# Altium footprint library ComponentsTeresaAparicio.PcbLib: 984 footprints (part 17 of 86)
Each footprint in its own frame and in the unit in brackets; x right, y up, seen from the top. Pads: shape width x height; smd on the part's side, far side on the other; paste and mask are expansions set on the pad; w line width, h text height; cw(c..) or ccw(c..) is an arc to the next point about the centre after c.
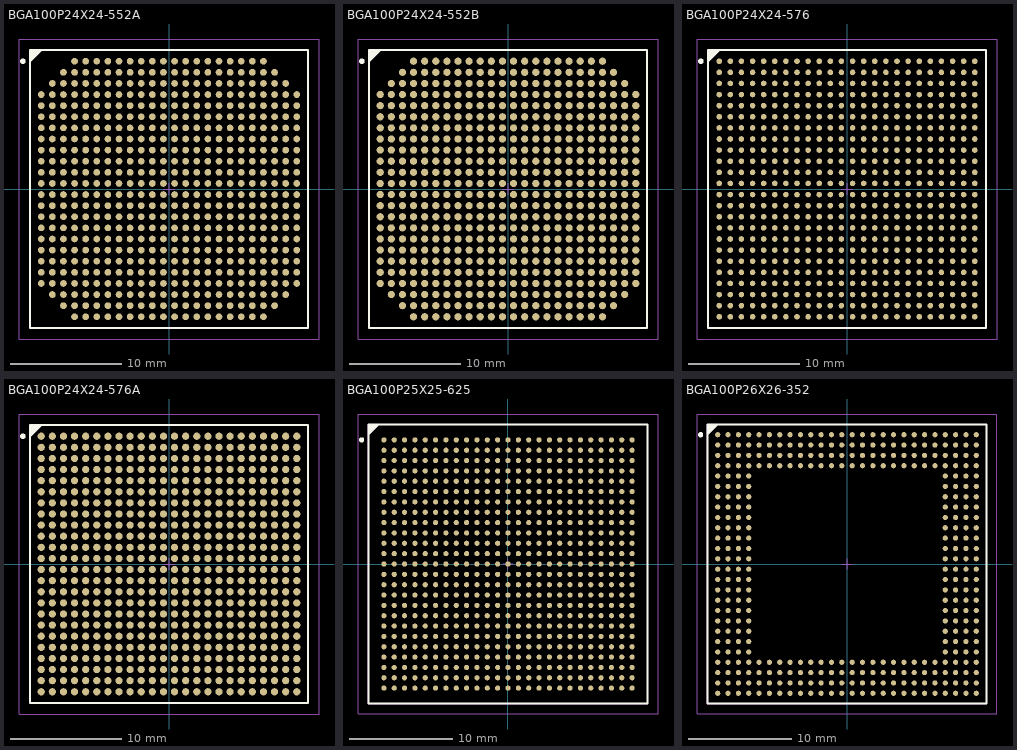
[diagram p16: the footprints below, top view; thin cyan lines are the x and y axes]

## BGA100P24X24-552A [mm] "BGA, 552-Leads, Body 25x25mm, Pitch 1mm"
height 3.49
pads (552):
  round 0.6 smd: A4(-8.5,11.5) A5(-7.5,11.5) A6(-6.5,11.5) A7(-5.5,11.5) A8(-4.5,11.5) A9(-3.5,11.5) A10(-2.5,11.5) A11(-1.5,11.5) A12(-0.5,11.5) A13(0.5,11.5) A14(1.5,11.5) A15(2.5,11.5) A16(3.5,11.5) A17(4.5,11.5) A18(5.5,11.5) A19(6.5,11.5) A20(7.5,11.5) A21(8.5,11.5) AA1(-11.5,-8.5) AA2(-10.5,-8.5) AA3(-9.5,-8.5) AA4(-8.5,-8.5) AA5(-7.5,-8.5) AA6(-6.5,-8.5) AA7(-5.5,-8.5) AA8(-4.5,-8.5) AA9(-3.5,-8.5) AA10(-2.5,-8.5) AA11(-1.5,-8.5) AA12(-0.5,-8.5) AA13(0.5,-8.5) AA14(1.5,-8.5) AA15(2.5,-8.5) AA16(3.5,-8.5) AA17(4.5,-8.5) AA18(5.5,-8.5) AA19(6.5,-8.5) AA20(7.5,-8.5) AA21(8.5,-8.5) AA22(9.5,-8.5) AA23(10.5,-8.5) AA24(11.5,-8.5) AB2(-10.5,-9.5) AB3(-9.5,-9.5) AB4(-8.5,-9.5) AB5(-7.5,-9.5) AB6(-6.5,-9.5) AB7(-5.5,-9.5) AB8(-4.5,-9.5) AB9(-3.5,-9.5) AB10(-2.5,-9.5) AB11(-1.5,-9.5) AB12(-0.5,-9.5) AB13(0.5,-9.5) AB14(1.5,-9.5) AB15(2.5,-9.5) AB16(3.5,-9.5) AB17(4.5,-9.5) AB18(5.5,-9.5) AB19(6.5,-9.5) AB20(7.5,-9.5) AB21(8.5,-9.5) AB22(9.5,-9.5) AB23(10.5,-9.5) AC3(-9.5,-10.5) AC4(-8.5,-10.5) AC5(-7.5,-10.5) AC6(-6.5,-10.5) AC7(-5.5,-10.5) AC8(-4.5,-10.5) AC9(-3.5,-10.5) AC10(-2.5,-10.5) AC11(-1.5,-10.5) AC12(-0.5,-10.5) AC13(0.5,-10.5) AC14(1.5,-10.5) AC15(2.5,-10.5) AC16(3.5,-10.5) AC17(4.5,-10.5) AC18(5.5,-10.5) AC19(6.5,-10.5) AC20(7.5,-10.5) AC21(8.5,-10.5) AC22(9.5,-10.5) AD4(-8.5,-11.5) AD5(-7.5,-11.5) AD6(-6.5,-11.5) AD7(-5.5,-11.5) AD8(-4.5,-11.5) AD9(-3.5,-11.5) AD10(-2.5,-11.5) AD11(-1.5,-11.5) AD12(-0.5,-11.5) AD13(0.5,-11.5) AD14(1.5,-11.5) AD15(2.5,-11.5) AD16(3.5,-11.5) AD17(4.5,-11.5) AD18(5.5,-11.5) AD19(6.5,-11.5) AD20(7.5,-11.5) AD21(8.5,-11.5) B3(-9.5,10.5) B4(-8.5,10.5) B5(-7.5,10.5) B6(-6.5,10.5) B7(-5.5,10.5) B8(-4.5,10.5) B9(-3.5,10.5) B10(-2.5,10.5) B11(-1.5,10.5) B12(-0.5,10.5) B13(0.5,10.5) B14(1.5,10.5) B15(2.5,10.5) B16(3.5,10.5) B17(4.5,10.5) B18(5.5,10.5) B19(6.5,10.5) B20(7.5,10.5) B21(8.5,10.5) B22(9.5,10.5) C2(-10.5,9.5) C3(-9.5,9.5) C4(-8.5,9.5) C5(-7.5,9.5) C6(-6.5,9.5) C7(-5.5,9.5) C8(-4.5,9.5) C9(-3.5,9.5) C10(-2.5,9.5) C11(-1.5,9.5) C12(-0.5,9.5) C13(0.5,9.5) C14(1.5,9.5) C15(2.5,9.5) C16(3.5,9.5) C17(4.5,9.5) C18(5.5,9.5) C19(6.5,9.5) C20(7.5,9.5) C21(8.5,9.5) C22(9.5,9.5) C23(10.5,9.5) D1(-11.5,8.5) D2(-10.5,8.5) D3(-9.5,8.5) D4(-8.5,8.5) D5(-7.5,8.5) D6(-6.5,8.5) D7(-5.5,8.5) D8(-4.5,8.5) D9(-3.5,8.5) D10(-2.5,8.5) D11(-1.5,8.5) D12(-0.5,8.5) D13(0.5,8.5) D14(1.5,8.5) D15(2.5,8.5) D16(3.5,8.5) D17(4.5,8.5) D18(5.5,8.5) D19(6.5,8.5) D20(7.5,8.5) D21(8.5,8.5) D22(9.5,8.5) D23(10.5,8.5) D24(11.5,8.5) E1(-11.5,7.5) E2(-10.5,7.5) E3(-9.5,7.5) E4(-8.5,7.5) E5(-7.5,7.5) E6(-6.5,7.5) E7(-5.5,7.5) E8(-4.5,7.5) E9(-3.5,7.5) E10(-2.5,7.5) E11(-1.5,7.5) E12(-0.5,7.5) E13(0.5,7.5) E14(1.5,7.5) E15(2.5,7.5) E16(3.5,7.5) E17(4.5,7.5) E18(5.5,7.5) E19(6.5,7.5) E20(7.5,7.5) E21(8.5,7.5) E22(9.5,7.5) E23(10.5,7.5) E24(11.5,7.5) F1(-11.5,6.5) F2(-10.5,6.5) F3(-9.5,6.5) F4(-8.5,6.5) F5(-7.5,6.5) F6(-6.5,6.5) F7(-5.5,6.5) F8(-4.5,6.5) F9(-3.5,6.5) F10(-2.5,6.5) F11(-1.5,6.5) F12(-0.5,6.5) F13(0.5,6.5) F14(1.5,6.5) F15(2.5,6.5) F16(3.5,6.5) F17(4.5,6.5) F18(5.5,6.5) F19(6.5,6.5) F20(7.5,6.5) F21(8.5,6.5) F22(9.5,6.5) F23(10.5,6.5) F24(11.5,6.5) G1(-11.5,5.5) G2(-10.5,5.5) G3(-9.5,5.5) G4(-8.5,5.5) G5(-7.5,5.5) G6(-6.5,5.5) G7(-5.5,5.5) G8(-4.5,5.5) G9(-3.5,5.5) G10(-2.5,5.5) G11(-1.5,5.5) G12(-0.5,5.5) G13(0.5,5.5) G14(1.5,5.5) G15(2.5,5.5) G16(3.5,5.5) G17(4.5,5.5) G18(5.5,5.5) G19(6.5,5.5) G20(7.5,5.5) G21(8.5,5.5) G22(9.5,5.5) G23(10.5,5.5) G24(11.5,5.5) H1(-11.5,4.5) H2(-10.5,4.5) H3(-9.5,4.5) H4(-8.5,4.5) H5(-7.5,4.5) H6(-6.5,4.5) H7(-5.5,4.5) H8(-4.5,4.5) H9(-3.5,4.5) H10(-2.5,4.5) H11(-1.5,4.5) H12(-0.5,4.5) H13(0.5,4.5) H14(1.5,4.5) H15(2.5,4.5) H16(3.5,4.5) H17(4.5,4.5) H18(5.5,4.5) H19(6.5,4.5) H20(7.5,4.5) H21(8.5,4.5) H22(9.5,4.5) H23(10.5,4.5) H24(11.5,4.5) J1(-11.5,3.5) J2(-10.5,3.5) J3(-9.5,3.5) J4(-8.5,3.5) J5(-7.5,3.5) J6(-6.5,3.5) J7(-5.5,3.5) J8(-4.5,3.5) J9(-3.5,3.5) J10(-2.5,3.5) J11(-1.5,3.5) J12(-0.5,3.5) J13(0.5,3.5) J14(1.5,3.5) J15(2.5,3.5) J16(3.5,3.5) J17(4.5,3.5) J18(5.5,3.5) J19(6.5,3.5) J20(7.5,3.5) J21(8.5,3.5) J22(9.5,3.5) J23(10.5,3.5) J24(11.5,3.5) K1(-11.5,2.5) K2(-10.5,2.5) K3(-9.5,2.5) K4(-8.5,2.5) K5(-7.5,2.5) K6(-6.5,2.5) K7(-5.5,2.5) K8(-4.5,2.5) K9(-3.5,2.5) K10(-2.5,2.5) K11(-1.5,2.5) K12(-0.5,2.5) K13(0.5,2.5) K14(1.5,2.5) K15(2.5,2.5) K16(3.5,2.5) K17(4.5,2.5) K18(5.5,2.5) K19(6.5,2.5) K20(7.5,2.5) K21(8.5,2.5) K22(9.5,2.5) K23(10.5,2.5) K24(11.5,2.5) L1(-11.5,1.5) L2(-10.5,1.5) L3(-9.5,1.5) L4(-8.5,1.5) L5(-7.5,1.5) L6(-6.5,1.5) L7(-5.5,1.5) L8(-4.5,1.5) L9(-3.5,1.5) L10(-2.5,1.5) L11(-1.5,1.5) L12(-0.5,1.5) L13(0.5,1.5) L14(1.5,1.5) L15(2.5,1.5) L16(3.5,1.5) L17(4.5,1.5) L18(5.5,1.5) L19(6.5,1.5) L20(7.5,1.5) L21(8.5,1.5) L22(9.5,1.5) L23(10.5,1.5) L24(11.5,1.5) M1(-11.5,0.5) M2(-10.5,0.5) M3(-9.5,0.5) M4(-8.5,0.5) M5(-7.5,0.5) M6(-6.5,0.5) M7(-5.5,0.5) M8(-4.5,0.5) M9(-3.5,0.5) M10(-2.5,0.5) M11(-1.5,0.5) M12(-0.5,0.5) M13(0.5,0.5) M14(1.5,0.5) M15(2.5,0.5) M16(3.5,0.5) M17(4.5,0.5) M18(5.5,0.5) M19(6.5,0.5) M20(7.5,0.5) M21(8.5,0.5) M22(9.5,0.5) M23(10.5,0.5) M24(11.5,0.5) N1(-11.5,-0.5) N2(-10.5,-0.5) N3(-9.5,-0.5) N4(-8.5,-0.5) N5(-7.5,-0.5) N6(-6.5,-0.5) N7(-5.5,-0.5) N8(-4.5,-0.5) N9(-3.5,-0.5) N10(-2.5,-0.5) N11(-1.5,-0.5) N12(-0.5,-0.5) N13(0.5,-0.5) N14(1.5,-0.5) N15(2.5,-0.5) N16(3.5,-0.5) N17(4.5,-0.5) N18(5.5,-0.5) N19(6.5,-0.5) N20(7.5,-0.5) N21(8.5,-0.5) N22(9.5,-0.5) N23(10.5,-0.5) N24(11.5,-0.5) P1(-11.5,-1.5) P2(-10.5,-1.5) P3(-9.5,-1.5) P4(-8.5,-1.5) P5(-7.5,-1.5) P6(-6.5,-1.5) P7(-5.5,-1.5) P8(-4.5,-1.5) P9(-3.5,-1.5) P10(-2.5,-1.5) P11(-1.5,-1.5) P12(-0.5,-1.5) P13(0.5,-1.5) P14(1.5,-1.5) P15(2.5,-1.5) P16(3.5,-1.5) P17(4.5,-1.5) P18(5.5,-1.5) P19(6.5,-1.5) P20(7.5,-1.5) P21(8.5,-1.5) P22(9.5,-1.5) P23(10.5,-1.5) P24(11.5,-1.5) R1(-11.5,-2.5) R2(-10.5,-2.5) R3(-9.5,-2.5) R4(-8.5,-2.5) R5(-7.5,-2.5) R6(-6.5,-2.5) R7(-5.5,-2.5) R8(-4.5,-2.5) R9(-3.5,-2.5) R10(-2.5,-2.5) R11(-1.5,-2.5) R12(-0.5,-2.5) R13(0.5,-2.5) R14(1.5,-2.5) R15(2.5,-2.5) R16(3.5,-2.5) R17(4.5,-2.5) R18(5.5,-2.5) R19(6.5,-2.5) R20(7.5,-2.5) R21(8.5,-2.5) R22(9.5,-2.5) R23(10.5,-2.5) R24(11.5,-2.5) T1(-11.5,-3.5) T2(-10.5,-3.5) T3(-9.5,-3.5) T4(-8.5,-3.5) T5(-7.5,-3.5) T6(-6.5,-3.5) T7(-5.5,-3.5) T8(-4.5,-3.5) T9(-3.5,-3.5) T10(-2.5,-3.5) T11(-1.5,-3.5) T12(-0.5,-3.5) T13(0.5,-3.5) T14(1.5,-3.5) T15(2.5,-3.5) T16(3.5,-3.5) T17(4.5,-3.5) T18(5.5,-3.5) T19(6.5,-3.5) T20(7.5,-3.5) T21(8.5,-3.5) T22(9.5,-3.5) T23(10.5,-3.5) T24(11.5,-3.5) U1(-11.5,-4.5) U2(-10.5,-4.5) U3(-9.5,-4.5) U4(-8.5,-4.5) U5(-7.5,-4.5) U6(-6.5,-4.5) U7(-5.5,-4.5) U8(-4.5,-4.5) U9(-3.5,-4.5) U10(-2.5,-4.5) U11(-1.5,-4.5) U12(-0.5,-4.5) U13(0.5,-4.5) U14(1.5,-4.5) U15(2.5,-4.5) U16(3.5,-4.5) U17(4.5,-4.5) U18(5.5,-4.5) U19(6.5,-4.5) U20(7.5,-4.5) U21(8.5,-4.5) U22(9.5,-4.5) U23(10.5,-4.5) U24(11.5,-4.5) V1(-11.5,-5.5) V2(-10.5,-5.5) V3(-9.5,-5.5) V4(-8.5,-5.5) V5(-7.5,-5.5) V6(-6.5,-5.5) V7(-5.5,-5.5) V8(-4.5,-5.5) V9(-3.5,-5.5) V10(-2.5,-5.5) V11(-1.5,-5.5) V12(-0.5,-5.5) V13(0.5,-5.5) V14(1.5,-5.5) V15(2.5,-5.5) V16(3.5,-5.5) V17(4.5,-5.5) V18(5.5,-5.5) V19(6.5,-5.5) V20(7.5,-5.5) V21(8.5,-5.5) V22(9.5,-5.5) V23(10.5,-5.5) V24(11.5,-5.5) W1(-11.5,-6.5) W2(-10.5,-6.5) W3(-9.5,-6.5) W4(-8.5,-6.5) W5(-7.5,-6.5) W6(-6.5,-6.5) W7(-5.5,-6.5) W8(-4.5,-6.5) W9(-3.5,-6.5) W10(-2.5,-6.5) W11(-1.5,-6.5) W12(-0.5,-6.5) W13(0.5,-6.5) W14(1.5,-6.5) W15(2.5,-6.5) W16(3.5,-6.5) W17(4.5,-6.5) W18(5.5,-6.5) W19(6.5,-6.5) W20(7.5,-6.5) W21(8.5,-6.5) W22(9.5,-6.5) W23(10.5,-6.5) W24(11.5,-6.5) Y1(-11.5,-7.5) Y2(-10.5,-7.5) Y3(-9.5,-7.5) Y4(-8.5,-7.5) Y5(-7.5,-7.5) Y6(-6.5,-7.5) Y7(-5.5,-7.5) Y8(-4.5,-7.5) Y9(-3.5,-7.5) Y10(-2.5,-7.5) Y11(-1.5,-7.5) Y12(-0.5,-7.5) Y13(0.5,-7.5) Y14(1.5,-7.5) Y15(2.5,-7.5) Y16(3.5,-7.5) Y17(4.5,-7.5) Y18(5.5,-7.5) Y19(6.5,-7.5) Y20(7.5,-7.5) Y21(8.5,-7.5) Y22(9.5,-7.5) Y23(10.5,-7.5) Y24(11.5,-7.5)
Top Overlay:
  circle w0.25: c-13.15,11.5 r0.125
  region: -11.5,12.5 -12.5,11.5 -12.5,12.5
  lines w0.2: -12.5,11.5 -11.5,12.5 ; -12.5,-12.5 -12.5,12.5 12.5,12.5 12.5,-12.5 -12.5,-12.5
Mechanical 13:
  lines w0.1: -12.5,-12.5 -12.5,12.5 12.5,12.5 12.5,-12.5 -12.5,-12.5
Mechanical 15:
  lines w0.1: -0.5,0 0.5,0 ; 0,-0.5 0,0.5 ; -13.5,-13.5 -13.5,13.5 13.5,13.5 13.5,-13.5 -13.5,-13.5
3D body: height 0, standoff 0, extent -12.5,-12.5 12.5,12.5

## BGA100P24X24-552B [mm] "BGA, 552-Leads, Body 25x25mm, Pitch 1mm"
height 3.8
pads (552):
  round 0.65 smd: A4(-8.5,11.5) A5(-7.5,11.5) A6(-6.5,11.5) A7(-5.5,11.5) A8(-4.5,11.5) A9(-3.5,11.5) A10(-2.5,11.5) A11(-1.5,11.5) A12(-0.5,11.5) A13(0.5,11.5) A14(1.5,11.5) A15(2.5,11.5) A16(3.5,11.5) A17(4.5,11.5) A18(5.5,11.5) A19(6.5,11.5) A20(7.5,11.5) A21(8.5,11.5) AA1(-11.5,-8.5) AA2(-10.5,-8.5) AA3(-9.5,-8.5) AA4(-8.5,-8.5) AA5(-7.5,-8.5) AA6(-6.5,-8.5) AA7(-5.5,-8.5) AA8(-4.5,-8.5) AA9(-3.5,-8.5) AA10(-2.5,-8.5) AA11(-1.5,-8.5) AA12(-0.5,-8.5) AA13(0.5,-8.5) AA14(1.5,-8.5) AA15(2.5,-8.5) AA16(3.5,-8.5) AA17(4.5,-8.5) AA18(5.5,-8.5) AA19(6.5,-8.5) AA20(7.5,-8.5) AA21(8.5,-8.5) AA22(9.5,-8.5) AA23(10.5,-8.5) AA24(11.5,-8.5) AB2(-10.5,-9.5) AB3(-9.5,-9.5) AB4(-8.5,-9.5) AB5(-7.5,-9.5) AB6(-6.5,-9.5) AB7(-5.5,-9.5) AB8(-4.5,-9.5) AB9(-3.5,-9.5) AB10(-2.5,-9.5) AB11(-1.5,-9.5) AB12(-0.5,-9.5) AB13(0.5,-9.5) AB14(1.5,-9.5) AB15(2.5,-9.5) AB16(3.5,-9.5) AB17(4.5,-9.5) AB18(5.5,-9.5) AB19(6.5,-9.5) AB20(7.5,-9.5) AB21(8.5,-9.5) AB22(9.5,-9.5) AB23(10.5,-9.5) AC3(-9.5,-10.5) AC4(-8.5,-10.5) AC5(-7.5,-10.5) AC6(-6.5,-10.5) AC7(-5.5,-10.5) AC8(-4.5,-10.5) AC9(-3.5,-10.5) AC10(-2.5,-10.5) AC11(-1.5,-10.5) AC12(-0.5,-10.5) AC13(0.5,-10.5) AC14(1.5,-10.5) AC15(2.5,-10.5) AC16(3.5,-10.5) AC17(4.5,-10.5) AC18(5.5,-10.5) AC19(6.5,-10.5) AC20(7.5,-10.5) AC21(8.5,-10.5) AC22(9.5,-10.5) AD4(-8.5,-11.5) AD5(-7.5,-11.5) AD6(-6.5,-11.5) AD7(-5.5,-11.5) AD8(-4.5,-11.5) AD9(-3.5,-11.5) AD10(-2.5,-11.5) AD11(-1.5,-11.5) AD12(-0.5,-11.5) AD13(0.5,-11.5) AD14(1.5,-11.5) AD15(2.5,-11.5) AD16(3.5,-11.5) AD17(4.5,-11.5) AD18(5.5,-11.5) AD19(6.5,-11.5) AD20(7.5,-11.5) AD21(8.5,-11.5) B3(-9.5,10.5) B4(-8.5,10.5) B5(-7.5,10.5) B6(-6.5,10.5) B7(-5.5,10.5) B8(-4.5,10.5) B9(-3.5,10.5) B10(-2.5,10.5) B11(-1.5,10.5) B12(-0.5,10.5) B13(0.5,10.5) B14(1.5,10.5) B15(2.5,10.5) B16(3.5,10.5) B17(4.5,10.5) B18(5.5,10.5) B19(6.5,10.5) B20(7.5,10.5) B21(8.5,10.5) B22(9.5,10.5) C2(-10.5,9.5) C3(-9.5,9.5) C4(-8.5,9.5) C5(-7.5,9.5) C6(-6.5,9.5) C7(-5.5,9.5) C8(-4.5,9.5) C9(-3.5,9.5) C10(-2.5,9.5) C11(-1.5,9.5) C12(-0.5,9.5) C13(0.5,9.5) C14(1.5,9.5) C15(2.5,9.5) C16(3.5,9.5) C17(4.5,9.5) C18(5.5,9.5) C19(6.5,9.5) C20(7.5,9.5) C21(8.5,9.5) C22(9.5,9.5) C23(10.5,9.5) D1(-11.5,8.5) D2(-10.5,8.5) D3(-9.5,8.5) D4(-8.5,8.5) D5(-7.5,8.5) D6(-6.5,8.5) D7(-5.5,8.5) D8(-4.5,8.5) D9(-3.5,8.5) D10(-2.5,8.5) D11(-1.5,8.5) D12(-0.5,8.5) D13(0.5,8.5) D14(1.5,8.5) D15(2.5,8.5) D16(3.5,8.5) D17(4.5,8.5) D18(5.5,8.5) D19(6.5,8.5) D20(7.5,8.5) D21(8.5,8.5) D22(9.5,8.5) D23(10.5,8.5) D24(11.5,8.5) E1(-11.5,7.5) E2(-10.5,7.5) E3(-9.5,7.5) E4(-8.5,7.5) E5(-7.5,7.5) E6(-6.5,7.5) E7(-5.5,7.5) E8(-4.5,7.5) E9(-3.5,7.5) E10(-2.5,7.5) E11(-1.5,7.5) E12(-0.5,7.5) E13(0.5,7.5) E14(1.5,7.5) E15(2.5,7.5) E16(3.5,7.5) E17(4.5,7.5) E18(5.5,7.5) E19(6.5,7.5) E20(7.5,7.5) E21(8.5,7.5) E22(9.5,7.5) E23(10.5,7.5) E24(11.5,7.5) F1(-11.5,6.5) F2(-10.5,6.5) F3(-9.5,6.5) F4(-8.5,6.5) F5(-7.5,6.5) F6(-6.5,6.5) F7(-5.5,6.5) F8(-4.5,6.5) F9(-3.5,6.5) F10(-2.5,6.5) F11(-1.5,6.5) F12(-0.5,6.5) F13(0.5,6.5) F14(1.5,6.5) F15(2.5,6.5) F16(3.5,6.5) F17(4.5,6.5) F18(5.5,6.5) F19(6.5,6.5) F20(7.5,6.5) F21(8.5,6.5) F22(9.5,6.5) F23(10.5,6.5) F24(11.5,6.5) G1(-11.5,5.5) G2(-10.5,5.5) G3(-9.5,5.5) G4(-8.5,5.5) G5(-7.5,5.5) G6(-6.5,5.5) G7(-5.5,5.5) G8(-4.5,5.5) G9(-3.5,5.5) G10(-2.5,5.5) G11(-1.5,5.5) G12(-0.5,5.5) G13(0.5,5.5) G14(1.5,5.5) G15(2.5,5.5) G16(3.5,5.5) G17(4.5,5.5) G18(5.5,5.5) G19(6.5,5.5) G20(7.5,5.5) G21(8.5,5.5) G22(9.5,5.5) G23(10.5,5.5) G24(11.5,5.5) H1(-11.5,4.5) H2(-10.5,4.5) H3(-9.5,4.5) H4(-8.5,4.5) H5(-7.5,4.5) H6(-6.5,4.5) H7(-5.5,4.5) H8(-4.5,4.5) H9(-3.5,4.5) H10(-2.5,4.5) H11(-1.5,4.5) H12(-0.5,4.5) H13(0.5,4.5) H14(1.5,4.5) H15(2.5,4.5) H16(3.5,4.5) H17(4.5,4.5) H18(5.5,4.5) H19(6.5,4.5) H20(7.5,4.5) H21(8.5,4.5) H22(9.5,4.5) H23(10.5,4.5) H24(11.5,4.5) J1(-11.5,3.5) J2(-10.5,3.5) J3(-9.5,3.5) J4(-8.5,3.5) J5(-7.5,3.5) J6(-6.5,3.5) J7(-5.5,3.5) J8(-4.5,3.5) J9(-3.5,3.5) J10(-2.5,3.5) J11(-1.5,3.5) J12(-0.5,3.5) J13(0.5,3.5) J14(1.5,3.5) J15(2.5,3.5) J16(3.5,3.5) J17(4.5,3.5) J18(5.5,3.5) J19(6.5,3.5) J20(7.5,3.5) J21(8.5,3.5) J22(9.5,3.5) J23(10.5,3.5) J24(11.5,3.5) K1(-11.5,2.5) K2(-10.5,2.5) K3(-9.5,2.5) K4(-8.5,2.5) K5(-7.5,2.5) K6(-6.5,2.5) K7(-5.5,2.5) K8(-4.5,2.5) K9(-3.5,2.5) K10(-2.5,2.5) K11(-1.5,2.5) K12(-0.5,2.5) K13(0.5,2.5) K14(1.5,2.5) K15(2.5,2.5) K16(3.5,2.5) K17(4.5,2.5) K18(5.5,2.5) K19(6.5,2.5) K20(7.5,2.5) K21(8.5,2.5) K22(9.5,2.5) K23(10.5,2.5) K24(11.5,2.5) L1(-11.5,1.5) L2(-10.5,1.5) L3(-9.5,1.5) L4(-8.5,1.5) L5(-7.5,1.5) L6(-6.5,1.5) L7(-5.5,1.5) L8(-4.5,1.5) L9(-3.5,1.5) L10(-2.5,1.5) L11(-1.5,1.5) L12(-0.5,1.5) L13(0.5,1.5) L14(1.5,1.5) L15(2.5,1.5) L16(3.5,1.5) L17(4.5,1.5) L18(5.5,1.5) L19(6.5,1.5) L20(7.5,1.5) L21(8.5,1.5) L22(9.5,1.5) L23(10.5,1.5) L24(11.5,1.5) M1(-11.5,0.5) M2(-10.5,0.5) M3(-9.5,0.5) M4(-8.5,0.5) M5(-7.5,0.5) M6(-6.5,0.5) M7(-5.5,0.5) M8(-4.5,0.5) M9(-3.5,0.5) M10(-2.5,0.5) M11(-1.5,0.5) M12(-0.5,0.5) M13(0.5,0.5) M14(1.5,0.5) M15(2.5,0.5) M16(3.5,0.5) M17(4.5,0.5) M18(5.5,0.5) M19(6.5,0.5) M20(7.5,0.5) M21(8.5,0.5) M22(9.5,0.5) M23(10.5,0.5) M24(11.5,0.5) N1(-11.5,-0.5) N2(-10.5,-0.5) N3(-9.5,-0.5) N4(-8.5,-0.5) N5(-7.5,-0.5) N6(-6.5,-0.5) N7(-5.5,-0.5) N8(-4.5,-0.5) N9(-3.5,-0.5) N10(-2.5,-0.5) N11(-1.5,-0.5) N12(-0.5,-0.5) N13(0.5,-0.5) N14(1.5,-0.5) N15(2.5,-0.5) N16(3.5,-0.5) N17(4.5,-0.5) N18(5.5,-0.5) N19(6.5,-0.5) N20(7.5,-0.5) N21(8.5,-0.5) N22(9.5,-0.5) N23(10.5,-0.5) N24(11.5,-0.5) P1(-11.5,-1.5) P2(-10.5,-1.5) P3(-9.5,-1.5) P4(-8.5,-1.5) P5(-7.5,-1.5) P6(-6.5,-1.5) P7(-5.5,-1.5) P8(-4.5,-1.5) P9(-3.5,-1.5) P10(-2.5,-1.5) P11(-1.5,-1.5) P12(-0.5,-1.5) P13(0.5,-1.5) P14(1.5,-1.5) P15(2.5,-1.5) P16(3.5,-1.5) P17(4.5,-1.5) P18(5.5,-1.5) P19(6.5,-1.5) P20(7.5,-1.5) P21(8.5,-1.5) P22(9.5,-1.5) P23(10.5,-1.5) P24(11.5,-1.5) R1(-11.5,-2.5) R2(-10.5,-2.5) R3(-9.5,-2.5) R4(-8.5,-2.5) R5(-7.5,-2.5) R6(-6.5,-2.5) R7(-5.5,-2.5) R8(-4.5,-2.5) R9(-3.5,-2.5) R10(-2.5,-2.5) R11(-1.5,-2.5) R12(-0.5,-2.5) R13(0.5,-2.5) R14(1.5,-2.5) R15(2.5,-2.5) R16(3.5,-2.5) R17(4.5,-2.5) R18(5.5,-2.5) R19(6.5,-2.5) R20(7.5,-2.5) R21(8.5,-2.5) R22(9.5,-2.5) R23(10.5,-2.5) R24(11.5,-2.5) T1(-11.5,-3.5) T2(-10.5,-3.5) T3(-9.5,-3.5) T4(-8.5,-3.5) T5(-7.5,-3.5) T6(-6.5,-3.5) T7(-5.5,-3.5) T8(-4.5,-3.5) T9(-3.5,-3.5) T10(-2.5,-3.5) T11(-1.5,-3.5) T12(-0.5,-3.5) T13(0.5,-3.5) T14(1.5,-3.5) T15(2.5,-3.5) T16(3.5,-3.5) T17(4.5,-3.5) T18(5.5,-3.5) T19(6.5,-3.5) T20(7.5,-3.5) T21(8.5,-3.5) T22(9.5,-3.5) T23(10.5,-3.5) T24(11.5,-3.5) U1(-11.5,-4.5) U2(-10.5,-4.5) U3(-9.5,-4.5) U4(-8.5,-4.5) U5(-7.5,-4.5) U6(-6.5,-4.5) U7(-5.5,-4.5) U8(-4.5,-4.5) U9(-3.5,-4.5) U10(-2.5,-4.5) U11(-1.5,-4.5) U12(-0.5,-4.5) U13(0.5,-4.5) U14(1.5,-4.5) U15(2.5,-4.5) U16(3.5,-4.5) U17(4.5,-4.5) U18(5.5,-4.5) U19(6.5,-4.5) U20(7.5,-4.5) U21(8.5,-4.5) U22(9.5,-4.5) U23(10.5,-4.5) U24(11.5,-4.5) V1(-11.5,-5.5) V2(-10.5,-5.5) V3(-9.5,-5.5) V4(-8.5,-5.5) V5(-7.5,-5.5) V6(-6.5,-5.5) V7(-5.5,-5.5) V8(-4.5,-5.5) V9(-3.5,-5.5) V10(-2.5,-5.5) V11(-1.5,-5.5) V12(-0.5,-5.5) V13(0.5,-5.5) V14(1.5,-5.5) V15(2.5,-5.5) V16(3.5,-5.5) V17(4.5,-5.5) V18(5.5,-5.5) V19(6.5,-5.5) V20(7.5,-5.5) V21(8.5,-5.5) V22(9.5,-5.5) V23(10.5,-5.5) V24(11.5,-5.5) W1(-11.5,-6.5) W2(-10.5,-6.5) W3(-9.5,-6.5) W4(-8.5,-6.5) W5(-7.5,-6.5) W6(-6.5,-6.5) W7(-5.5,-6.5) W8(-4.5,-6.5) W9(-3.5,-6.5) W10(-2.5,-6.5) W11(-1.5,-6.5) W12(-0.5,-6.5) W13(0.5,-6.5) W14(1.5,-6.5) W15(2.5,-6.5) W16(3.5,-6.5) W17(4.5,-6.5) W18(5.5,-6.5) W19(6.5,-6.5) W20(7.5,-6.5) W21(8.5,-6.5) W22(9.5,-6.5) W23(10.5,-6.5) W24(11.5,-6.5) Y1(-11.5,-7.5) Y2(-10.5,-7.5) Y3(-9.5,-7.5) Y4(-8.5,-7.5) Y5(-7.5,-7.5) Y6(-6.5,-7.5) Y7(-5.5,-7.5) Y8(-4.5,-7.5) Y9(-3.5,-7.5) Y10(-2.5,-7.5) Y11(-1.5,-7.5) Y12(-0.5,-7.5) Y13(0.5,-7.5) Y14(1.5,-7.5) Y15(2.5,-7.5) Y16(3.5,-7.5) Y17(4.5,-7.5) Y18(5.5,-7.5) Y19(6.5,-7.5) Y20(7.5,-7.5) Y21(8.5,-7.5) Y22(9.5,-7.5) Y23(10.5,-7.5) Y24(11.5,-7.5)
Top Overlay:
  circle w0.25: c-13.15,11.5 r0.125
  region: -11.525,12.5 -12.5,11.525 -12.5,12.5
  lines w0.2: -12.5,11.525 -11.525,12.5 ; -12.5,-12.5 12.5,-12.5 12.5,12.5 -12.5,12.5 -12.5,-12.5
Mechanical 13:
  lines w0.1: -12.5,-12.5 12.5,-12.5 12.5,12.5 -12.5,12.5 -12.5,-12.5
Mechanical 15:
  lines w0.1: -0.5,0 0.5,0 ; 0,-0.5 0,0.5 ; -13.5,-13.5 13.5,-13.5 13.5,13.5 -13.5,13.5 -13.5,-13.5
3D body: height 0, standoff 0, extent -12.5,-12.5 12.5,12.5

## BGA100P24X24-576 [mm] "BGA, 576-Leads, Body 25x25mm, Pitch 1mm"
height 3.5
pads (576):
  round 0.5 smd: A1(-11.5,11.5) A2(-10.5,11.5) A3(-9.5,11.5) A4(-8.5,11.5) A5(-7.5,11.5) A6(-6.5,11.5) A7(-5.5,11.5) A8(-4.5,11.5) A9(-3.5,11.5) A10(-2.5,11.5) A11(-1.5,11.5) A12(-0.5,11.5) A13(0.5,11.5) A14(1.5,11.5) A15(2.5,11.5) A16(3.5,11.5) A17(4.5,11.5) A18(5.5,11.5) A19(6.5,11.5) A20(7.5,11.5) A21(8.5,11.5) A22(9.5,11.5) A23(10.5,11.5) A24(11.5,11.5) AA1(-11.5,-8.5) AA2(-10.5,-8.5) AA3(-9.5,-8.5) AA4(-8.5,-8.5) AA5(-7.5,-8.5) AA6(-6.5,-8.5) AA7(-5.5,-8.5) AA8(-4.5,-8.5) AA9(-3.5,-8.5) AA10(-2.5,-8.5) AA11(-1.5,-8.5) AA12(-0.5,-8.5) AA13(0.5,-8.5) AA14(1.5,-8.5) AA15(2.5,-8.5) AA16(3.5,-8.5) AA17(4.5,-8.5) AA18(5.5,-8.5) AA19(6.5,-8.5) AA20(7.5,-8.5) AA21(8.5,-8.5) AA22(9.5,-8.5) AA23(10.5,-8.5) AA24(11.5,-8.5) AB1(-11.5,-9.5) AB2(-10.5,-9.5) AB3(-9.5,-9.5) AB4(-8.5,-9.5) AB5(-7.5,-9.5) AB6(-6.5,-9.5) AB7(-5.5,-9.5) AB8(-4.5,-9.5) AB9(-3.5,-9.5) AB10(-2.5,-9.5) AB11(-1.5,-9.5) AB12(-0.5,-9.5) AB13(0.5,-9.5) AB14(1.5,-9.5) AB15(2.5,-9.5) AB16(3.5,-9.5) AB17(4.5,-9.5) AB18(5.5,-9.5) AB19(6.5,-9.5) AB20(7.5,-9.5) AB21(8.5,-9.5) AB22(9.5,-9.5) AB23(10.5,-9.5) AB24(11.5,-9.5) AC1(-11.5,-10.5) AC2(-10.5,-10.5) AC3(-9.5,-10.5) AC4(-8.5,-10.5) AC5(-7.5,-10.5) AC6(-6.5,-10.5) AC7(-5.5,-10.5) AC8(-4.5,-10.5) AC9(-3.5,-10.5) AC10(-2.5,-10.5) AC11(-1.5,-10.5) AC12(-0.5,-10.5) AC13(0.5,-10.5) AC14(1.5,-10.5) AC15(2.5,-10.5) AC16(3.5,-10.5) AC17(4.5,-10.5) AC18(5.5,-10.5) AC19(6.5,-10.5) AC20(7.5,-10.5) AC21(8.5,-10.5) AC22(9.5,-10.5) AC23(10.5,-10.5) AC24(11.5,-10.5) AD1(-11.5,-11.5) AD2(-10.5,-11.5) AD3(-9.5,-11.5) AD4(-8.5,-11.5) AD5(-7.5,-11.5) AD6(-6.5,-11.5) AD7(-5.5,-11.5) AD8(-4.5,-11.5) AD9(-3.5,-11.5) AD10(-2.5,-11.5) AD11(-1.5,-11.5) AD12(-0.5,-11.5) AD13(0.5,-11.5) AD14(1.5,-11.5) AD15(2.5,-11.5) AD16(3.5,-11.5) AD17(4.5,-11.5) AD18(5.5,-11.5) AD19(6.5,-11.5) AD20(7.5,-11.5) AD21(8.5,-11.5) AD22(9.5,-11.5) AD23(10.5,-11.5) AD24(11.5,-11.5) B1(-11.5,10.5) B2(-10.5,10.5) B3(-9.5,10.5) B4(-8.5,10.5) B5(-7.5,10.5) B6(-6.5,10.5) B7(-5.5,10.5) B8(-4.5,10.5) B9(-3.5,10.5) B10(-2.5,10.5) B11(-1.5,10.5) B12(-0.5,10.5) B13(0.5,10.5) B14(1.5,10.5) B15(2.5,10.5) B16(3.5,10.5) B17(4.5,10.5) B18(5.5,10.5) B19(6.5,10.5) B20(7.5,10.5) B21(8.5,10.5) B22(9.5,10.5) B23(10.5,10.5) B24(11.5,10.5) C1(-11.5,9.5) C2(-10.5,9.5) C3(-9.5,9.5) C4(-8.5,9.5) C5(-7.5,9.5) C6(-6.5,9.5) C7(-5.5,9.5) C8(-4.5,9.5) C9(-3.5,9.5) C10(-2.5,9.5) C11(-1.5,9.5) C12(-0.5,9.5) C13(0.5,9.5) C14(1.5,9.5) C15(2.5,9.5) C16(3.5,9.5) C17(4.5,9.5) C18(5.5,9.5) C19(6.5,9.5) C20(7.5,9.5) C21(8.5,9.5) C22(9.5,9.5) C23(10.5,9.5) C24(11.5,9.5) D1(-11.5,8.5) D2(-10.5,8.5) D3(-9.5,8.5) D4(-8.5,8.5) D5(-7.5,8.5) D6(-6.5,8.5) D7(-5.5,8.5) D8(-4.5,8.5) D9(-3.5,8.5) D10(-2.5,8.5) D11(-1.5,8.5) D12(-0.5,8.5) D13(0.5,8.5) D14(1.5,8.5) D15(2.5,8.5) D16(3.5,8.5) D17(4.5,8.5) D18(5.5,8.5) D19(6.5,8.5) D20(7.5,8.5) D21(8.5,8.5) D22(9.5,8.5) D23(10.5,8.5) D24(11.5,8.5) E1(-11.5,7.5) E2(-10.5,7.5) E3(-9.5,7.5) E4(-8.5,7.5) E5(-7.5,7.5) E6(-6.5,7.5) E7(-5.5,7.5) E8(-4.5,7.5) E9(-3.5,7.5) E10(-2.5,7.5) E11(-1.5,7.5) E12(-0.5,7.5) E13(0.5,7.5) E14(1.5,7.5) E15(2.5,7.5) E16(3.5,7.5) E17(4.5,7.5) E18(5.5,7.5) E19(6.5,7.5) E20(7.5,7.5) E21(8.5,7.5) E22(9.5,7.5) E23(10.5,7.5) E24(11.5,7.5) F1(-11.5,6.5) F2(-10.5,6.5) F3(-9.5,6.5) F4(-8.5,6.5) F5(-7.5,6.5) F6(-6.5,6.5) F7(-5.5,6.5) F8(-4.5,6.5) F9(-3.5,6.5) F10(-2.5,6.5) F11(-1.5,6.5) F12(-0.5,6.5) F13(0.5,6.5) F14(1.5,6.5) F15(2.5,6.5) F16(3.5,6.5) F17(4.5,6.5) F18(5.5,6.5) F19(6.5,6.5) F20(7.5,6.5) F21(8.5,6.5) F22(9.5,6.5) F23(10.5,6.5) F24(11.5,6.5) G1(-11.5,5.5) G2(-10.5,5.5) G3(-9.5,5.5) G4(-8.5,5.5) G5(-7.5,5.5) G6(-6.5,5.5) G7(-5.5,5.5) G8(-4.5,5.5) G9(-3.5,5.5) G10(-2.5,5.5) G11(-1.5,5.5) G12(-0.5,5.5) G13(0.5,5.5) G14(1.5,5.5) G15(2.5,5.5) G16(3.5,5.5) G17(4.5,5.5) G18(5.5,5.5) G19(6.5,5.5) G20(7.5,5.5) G21(8.5,5.5) G22(9.5,5.5) G23(10.5,5.5) G24(11.5,5.5) H1(-11.5,4.5) H2(-10.5,4.5) H3(-9.5,4.5) H4(-8.5,4.5) H5(-7.5,4.5) H6(-6.5,4.5) H7(-5.5,4.5) H8(-4.5,4.5) H9(-3.5,4.5) H10(-2.5,4.5) H11(-1.5,4.5) H12(-0.5,4.5) H13(0.5,4.5) H14(1.5,4.5) H15(2.5,4.5) H16(3.5,4.5) H17(4.5,4.5) H18(5.5,4.5) H19(6.5,4.5) H20(7.5,4.5) H21(8.5,4.5) H22(9.5,4.5) H23(10.5,4.5) H24(11.5,4.5) J1(-11.5,3.5) J2(-10.5,3.5) J3(-9.5,3.5) J4(-8.5,3.5) J5(-7.5,3.5) J6(-6.5,3.5) J7(-5.5,3.5) J8(-4.5,3.5) J9(-3.5,3.5) J10(-2.5,3.5) J11(-1.5,3.5) J12(-0.5,3.5) J13(0.5,3.5) J14(1.5,3.5) J15(2.5,3.5) J16(3.5,3.5) J17(4.5,3.5) J18(5.5,3.5) J19(6.5,3.5) J20(7.5,3.5) J21(8.5,3.5) J22(9.5,3.5) J23(10.5,3.5) J24(11.5,3.5) K1(-11.5,2.5) K2(-10.5,2.5) K3(-9.5,2.5) K4(-8.5,2.5) K5(-7.5,2.5) K6(-6.5,2.5) K7(-5.5,2.5) K8(-4.5,2.5) K9(-3.5,2.5) K10(-2.5,2.5) K11(-1.5,2.5) K12(-0.5,2.5) K13(0.5,2.5) K14(1.5,2.5) K15(2.5,2.5) K16(3.5,2.5) K17(4.5,2.5) K18(5.5,2.5) K19(6.5,2.5) K20(7.5,2.5) K21(8.5,2.5) K22(9.5,2.5) K23(10.5,2.5) K24(11.5,2.5) L1(-11.5,1.5) L2(-10.5,1.5) L3(-9.5,1.5) L4(-8.5,1.5) L5(-7.5,1.5) L6(-6.5,1.5) L7(-5.5,1.5) L8(-4.5,1.5) L9(-3.5,1.5) L10(-2.5,1.5) L11(-1.5,1.5) L12(-0.5,1.5) L13(0.5,1.5) L14(1.5,1.5) L15(2.5,1.5) L16(3.5,1.5) L17(4.5,1.5) L18(5.5,1.5) L19(6.5,1.5) L20(7.5,1.5) L21(8.5,1.5) L22(9.5,1.5) L23(10.5,1.5) L24(11.5,1.5) M1(-11.5,0.5) M2(-10.5,0.5) M3(-9.5,0.5) M4(-8.5,0.5) M5(-7.5,0.5) M6(-6.5,0.5) M7(-5.5,0.5) M8(-4.5,0.5) M9(-3.5,0.5) M10(-2.5,0.5) M11(-1.5,0.5) M12(-0.5,0.5) M13(0.5,0.5) M14(1.5,0.5) M15(2.5,0.5) M16(3.5,0.5) M17(4.5,0.5) M18(5.5,0.5) M19(6.5,0.5) M20(7.5,0.5) M21(8.5,0.5) M22(9.5,0.5) M23(10.5,0.5) M24(11.5,0.5) N1(-11.5,-0.5) N2(-10.5,-0.5) N3(-9.5,-0.5) N4(-8.5,-0.5) N5(-7.5,-0.5) N6(-6.5,-0.5) N7(-5.5,-0.5) N8(-4.5,-0.5) N9(-3.5,-0.5) N10(-2.5,-0.5) N11(-1.5,-0.5) N12(-0.5,-0.5) N13(0.5,-0.5) N14(1.5,-0.5) N15(2.5,-0.5) N16(3.5,-0.5) N17(4.5,-0.5) N18(5.5,-0.5) N19(6.5,-0.5) N20(7.5,-0.5) N21(8.5,-0.5) N22(9.5,-0.5) N23(10.5,-0.5) N24(11.5,-0.5) P1(-11.5,-1.5) P2(-10.5,-1.5) P3(-9.5,-1.5) P4(-8.5,-1.5) P5(-7.5,-1.5) P6(-6.5,-1.5) P7(-5.5,-1.5) P8(-4.5,-1.5) P9(-3.5,-1.5) P10(-2.5,-1.5) P11(-1.5,-1.5) P12(-0.5,-1.5) P13(0.5,-1.5) P14(1.5,-1.5) P15(2.5,-1.5) P16(3.5,-1.5) P17(4.5,-1.5) P18(5.5,-1.5) P19(6.5,-1.5) P20(7.5,-1.5) P21(8.5,-1.5) P22(9.5,-1.5) P23(10.5,-1.5) P24(11.5,-1.5) R1(-11.5,-2.5) R2(-10.5,-2.5) R3(-9.5,-2.5) R4(-8.5,-2.5) R5(-7.5,-2.5) R6(-6.5,-2.5) R7(-5.5,-2.5) R8(-4.5,-2.5) R9(-3.5,-2.5) R10(-2.5,-2.5) R11(-1.5,-2.5) R12(-0.5,-2.5) R13(0.5,-2.5) R14(1.5,-2.5) R15(2.5,-2.5) R16(3.5,-2.5) R17(4.5,-2.5) R18(5.5,-2.5) R19(6.5,-2.5) R20(7.5,-2.5) R21(8.5,-2.5) R22(9.5,-2.5) R23(10.5,-2.5) R24(11.5,-2.5) T1(-11.5,-3.5) T2(-10.5,-3.5) T3(-9.5,-3.5) T4(-8.5,-3.5) T5(-7.5,-3.5) T6(-6.5,-3.5) T7(-5.5,-3.5) T8(-4.5,-3.5) T9(-3.5,-3.5) T10(-2.5,-3.5) T11(-1.5,-3.5) T12(-0.5,-3.5) T13(0.5,-3.5) T14(1.5,-3.5) T15(2.5,-3.5) T16(3.5,-3.5) T17(4.5,-3.5) T18(5.5,-3.5) T19(6.5,-3.5) T20(7.5,-3.5) T21(8.5,-3.5) T22(9.5,-3.5) T23(10.5,-3.5) T24(11.5,-3.5) U1(-11.5,-4.5) U2(-10.5,-4.5) U3(-9.5,-4.5) U4(-8.5,-4.5) U5(-7.5,-4.5) U6(-6.5,-4.5) U7(-5.5,-4.5) U8(-4.5,-4.5) U9(-3.5,-4.5) U10(-2.5,-4.5) U11(-1.5,-4.5) U12(-0.5,-4.5) U13(0.5,-4.5) U14(1.5,-4.5) U15(2.5,-4.5) U16(3.5,-4.5) U17(4.5,-4.5) U18(5.5,-4.5) U19(6.5,-4.5) U20(7.5,-4.5) U21(8.5,-4.5) U22(9.5,-4.5) U23(10.5,-4.5) U24(11.5,-4.5) V1(-11.5,-5.5) V2(-10.5,-5.5) V3(-9.5,-5.5) V4(-8.5,-5.5) V5(-7.5,-5.5) V6(-6.5,-5.5) V7(-5.5,-5.5) V8(-4.5,-5.5) V9(-3.5,-5.5) V10(-2.5,-5.5) V11(-1.5,-5.5) V12(-0.5,-5.5) V13(0.5,-5.5) V14(1.5,-5.5) V15(2.5,-5.5) V16(3.5,-5.5) V17(4.5,-5.5) V18(5.5,-5.5) V19(6.5,-5.5) V20(7.5,-5.5) V21(8.5,-5.5) V22(9.5,-5.5) V23(10.5,-5.5) V24(11.5,-5.5) W1(-11.5,-6.5) W2(-10.5,-6.5) W3(-9.5,-6.5) W4(-8.5,-6.5) W5(-7.5,-6.5) W6(-6.5,-6.5) W7(-5.5,-6.5) W8(-4.5,-6.5) W9(-3.5,-6.5) W10(-2.5,-6.5) W11(-1.5,-6.5) W12(-0.5,-6.5) W13(0.5,-6.5) W14(1.5,-6.5) W15(2.5,-6.5) W16(3.5,-6.5) W17(4.5,-6.5) W18(5.5,-6.5) W19(6.5,-6.5) W20(7.5,-6.5) W21(8.5,-6.5) W22(9.5,-6.5) W23(10.5,-6.5) W24(11.5,-6.5) Y1(-11.5,-7.5) Y2(-10.5,-7.5) Y3(-9.5,-7.5) Y4(-8.5,-7.5) Y5(-7.5,-7.5) Y6(-6.5,-7.5) Y7(-5.5,-7.5) Y8(-4.5,-7.5) Y9(-3.5,-7.5) Y10(-2.5,-7.5) Y11(-1.5,-7.5) Y12(-0.5,-7.5) Y13(0.5,-7.5) Y14(1.5,-7.5) Y15(2.5,-7.5) Y16(3.5,-7.5) Y17(4.5,-7.5) Y18(5.5,-7.5) Y19(6.5,-7.5) Y20(7.5,-7.5) Y21(8.5,-7.5) Y22(9.5,-7.5) Y23(10.5,-7.5) Y24(11.5,-7.5)
Top Overlay:
  circle w0.25: c-13.15,11.5 r0.125
  region: -11.5,12.5 -12.5,11.5 -12.5,12.5
  lines w0.2: -12.5,11.5 -11.5,12.5 ; -12.5,-12.5 -12.5,12.5 12.5,12.5 12.5,-12.5 -12.5,-12.5
Mechanical 13:
  lines w0.1: -12.5,-12.5 -12.5,12.5 12.5,12.5 12.5,-12.5 -12.5,-12.5
Mechanical 15:
  lines w0.1: -0.5,0 0.5,0 ; 0,-0.5 0,0.5 ; -13.5,-13.5 -13.5,13.5 13.5,13.5 13.5,-13.5 -13.5,-13.5
3D body: height 0, standoff 0, extent -12.5,-12.5 12.5,12.5

## BGA100P24X24-576A [mm] "BGA, 576-Leads, Body 25x25mm, Pitch 1mm"
height 3.17
pads (576):
  round 0.65 smd: A1(-11.5,11.5) A2(-10.5,11.5) A3(-9.5,11.5) A4(-8.5,11.5) A5(-7.5,11.5) A6(-6.5,11.5) A7(-5.5,11.5) A8(-4.5,11.5) A9(-3.5,11.5) A10(-2.5,11.5) A11(-1.5,11.5) A12(-0.5,11.5) A13(0.5,11.5) A14(1.5,11.5) A15(2.5,11.5) A16(3.5,11.5) A17(4.5,11.5) A18(5.5,11.5) A19(6.5,11.5) A20(7.5,11.5) A21(8.5,11.5) A22(9.5,11.5) A23(10.5,11.5) A24(11.5,11.5) AA1(-11.5,-8.5) AA2(-10.5,-8.5) AA3(-9.5,-8.5) AA4(-8.5,-8.5) AA5(-7.5,-8.5) AA6(-6.5,-8.5) AA7(-5.5,-8.5) AA8(-4.5,-8.5) AA9(-3.5,-8.5) AA10(-2.5,-8.5) AA11(-1.5,-8.5) AA12(-0.5,-8.5) AA13(0.5,-8.5) AA14(1.5,-8.5) AA15(2.5,-8.5) AA16(3.5,-8.5) AA17(4.5,-8.5) AA18(5.5,-8.5) AA19(6.5,-8.5) AA20(7.5,-8.5) AA21(8.5,-8.5) AA22(9.5,-8.5) AA23(10.5,-8.5) AA24(11.5,-8.5) AB1(-11.5,-9.5) AB2(-10.5,-9.5) AB3(-9.5,-9.5) AB4(-8.5,-9.5) AB5(-7.5,-9.5) AB6(-6.5,-9.5) AB7(-5.5,-9.5) AB8(-4.5,-9.5) AB9(-3.5,-9.5) AB10(-2.5,-9.5) AB11(-1.5,-9.5) AB12(-0.5,-9.5) AB13(0.5,-9.5) AB14(1.5,-9.5) AB15(2.5,-9.5) AB16(3.5,-9.5) AB17(4.5,-9.5) AB18(5.5,-9.5) AB19(6.5,-9.5) AB20(7.5,-9.5) AB21(8.5,-9.5) AB22(9.5,-9.5) AB23(10.5,-9.5) AB24(11.5,-9.5) AC1(-11.5,-10.5) AC2(-10.5,-10.5) AC3(-9.5,-10.5) AC4(-8.5,-10.5) AC5(-7.5,-10.5) AC6(-6.5,-10.5) AC7(-5.5,-10.5) AC8(-4.5,-10.5) AC9(-3.5,-10.5) AC10(-2.5,-10.5) AC11(-1.5,-10.5) AC12(-0.5,-10.5) AC13(0.5,-10.5) AC14(1.5,-10.5) AC15(2.5,-10.5) AC16(3.5,-10.5) AC17(4.5,-10.5) AC18(5.5,-10.5) AC19(6.5,-10.5) AC20(7.5,-10.5) AC21(8.5,-10.5) AC22(9.5,-10.5) AC23(10.5,-10.5) AC24(11.5,-10.5) AD1(-11.5,-11.5) AD2(-10.5,-11.5) AD3(-9.5,-11.5) AD4(-8.5,-11.5) AD5(-7.5,-11.5) AD6(-6.5,-11.5) AD7(-5.5,-11.5) AD8(-4.5,-11.5) AD9(-3.5,-11.5) AD10(-2.5,-11.5) AD11(-1.5,-11.5) AD12(-0.5,-11.5) AD13(0.5,-11.5) AD14(1.5,-11.5) AD15(2.5,-11.5) AD16(3.5,-11.5) AD17(4.5,-11.5) AD18(5.5,-11.5) AD19(6.5,-11.5) AD20(7.5,-11.5) AD21(8.5,-11.5) AD22(9.5,-11.5) AD23(10.5,-11.5) AD24(11.5,-11.5) B1(-11.5,10.5) B2(-10.5,10.5) B3(-9.5,10.5) B4(-8.5,10.5) B5(-7.5,10.5) B6(-6.5,10.5) B7(-5.5,10.5) B8(-4.5,10.5) B9(-3.5,10.5) B10(-2.5,10.5) B11(-1.5,10.5) B12(-0.5,10.5) B13(0.5,10.5) B14(1.5,10.5) B15(2.5,10.5) B16(3.5,10.5) B17(4.5,10.5) B18(5.5,10.5) B19(6.5,10.5) B20(7.5,10.5) B21(8.5,10.5) B22(9.5,10.5) B23(10.5,10.5) B24(11.5,10.5) C1(-11.5,9.5) C2(-10.5,9.5) C3(-9.5,9.5) C4(-8.5,9.5) C5(-7.5,9.5) C6(-6.5,9.5) C7(-5.5,9.5) C8(-4.5,9.5) C9(-3.5,9.5) C10(-2.5,9.5) C11(-1.5,9.5) C12(-0.5,9.5) C13(0.5,9.5) C14(1.5,9.5) C15(2.5,9.5) C16(3.5,9.5) C17(4.5,9.5) C18(5.5,9.5) C19(6.5,9.5) C20(7.5,9.5) C21(8.5,9.5) C22(9.5,9.5) C23(10.5,9.5) C24(11.5,9.5) D1(-11.5,8.5) D2(-10.5,8.5) D3(-9.5,8.5) D4(-8.5,8.5) D5(-7.5,8.5) D6(-6.5,8.5) D7(-5.5,8.5) D8(-4.5,8.5) D9(-3.5,8.5) D10(-2.5,8.5) D11(-1.5,8.5) D12(-0.5,8.5) D13(0.5,8.5) D14(1.5,8.5) D15(2.5,8.5) D16(3.5,8.5) D17(4.5,8.5) D18(5.5,8.5) D19(6.5,8.5) D20(7.5,8.5) D21(8.5,8.5) D22(9.5,8.5) D23(10.5,8.5) D24(11.5,8.5) E1(-11.5,7.5) E2(-10.5,7.5) E3(-9.5,7.5) E4(-8.5,7.5) E5(-7.5,7.5) E6(-6.5,7.5) E7(-5.5,7.5) E8(-4.5,7.5) E9(-3.5,7.5) E10(-2.5,7.5) E11(-1.5,7.5) E12(-0.5,7.5) E13(0.5,7.5) E14(1.5,7.5) E15(2.5,7.5) E16(3.5,7.5) E17(4.5,7.5) E18(5.5,7.5) E19(6.5,7.5) E20(7.5,7.5) E21(8.5,7.5) E22(9.5,7.5) E23(10.5,7.5) E24(11.5,7.5) F1(-11.5,6.5) F2(-10.5,6.5) F3(-9.5,6.5) F4(-8.5,6.5) F5(-7.5,6.5) F6(-6.5,6.5) F7(-5.5,6.5) F8(-4.5,6.5) F9(-3.5,6.5) F10(-2.5,6.5) F11(-1.5,6.5) F12(-0.5,6.5) F13(0.5,6.5) F14(1.5,6.5) F15(2.5,6.5) F16(3.5,6.5) F17(4.5,6.5) F18(5.5,6.5) F19(6.5,6.5) F20(7.5,6.5) F21(8.5,6.5) F22(9.5,6.5) F23(10.5,6.5) F24(11.5,6.5) G1(-11.5,5.5) G2(-10.5,5.5) G3(-9.5,5.5) G4(-8.5,5.5) G5(-7.5,5.5) G6(-6.5,5.5) G7(-5.5,5.5) G8(-4.5,5.5) G9(-3.5,5.5) G10(-2.5,5.5) G11(-1.5,5.5) G12(-0.5,5.5) G13(0.5,5.5) G14(1.5,5.5) G15(2.5,5.5) G16(3.5,5.5) G17(4.5,5.5) G18(5.5,5.5) G19(6.5,5.5) G20(7.5,5.5) G21(8.5,5.5) G22(9.5,5.5) G23(10.5,5.5) G24(11.5,5.5) H1(-11.5,4.5) H2(-10.5,4.5) H3(-9.5,4.5) H4(-8.5,4.5) H5(-7.5,4.5) H6(-6.5,4.5) H7(-5.5,4.5) H8(-4.5,4.5) H9(-3.5,4.5) H10(-2.5,4.5) H11(-1.5,4.5) H12(-0.5,4.5) H13(0.5,4.5) H14(1.5,4.5) H15(2.5,4.5) H16(3.5,4.5) H17(4.5,4.5) H18(5.5,4.5) H19(6.5,4.5) H20(7.5,4.5) H21(8.5,4.5) H22(9.5,4.5) H23(10.5,4.5) H24(11.5,4.5) J1(-11.5,3.5) J2(-10.5,3.5) J3(-9.5,3.5) J4(-8.5,3.5) J5(-7.5,3.5) J6(-6.5,3.5) J7(-5.5,3.5) J8(-4.5,3.5) J9(-3.5,3.5) J10(-2.5,3.5) J11(-1.5,3.5) J12(-0.5,3.5) J13(0.5,3.5) J14(1.5,3.5) J15(2.5,3.5) J16(3.5,3.5) J17(4.5,3.5) J18(5.5,3.5) J19(6.5,3.5) J20(7.5,3.5) J21(8.5,3.5) J22(9.5,3.5) J23(10.5,3.5) J24(11.5,3.5) K1(-11.5,2.5) K2(-10.5,2.5) K3(-9.5,2.5) K4(-8.5,2.5) K5(-7.5,2.5) K6(-6.5,2.5) K7(-5.5,2.5) K8(-4.5,2.5) K9(-3.5,2.5) K10(-2.5,2.5) K11(-1.5,2.5) K12(-0.5,2.5) K13(0.5,2.5) K14(1.5,2.5) K15(2.5,2.5) K16(3.5,2.5) K17(4.5,2.5) K18(5.5,2.5) K19(6.5,2.5) K20(7.5,2.5) K21(8.5,2.5) K22(9.5,2.5) K23(10.5,2.5) K24(11.5,2.5) L1(-11.5,1.5) L2(-10.5,1.5) L3(-9.5,1.5) L4(-8.5,1.5) L5(-7.5,1.5) L6(-6.5,1.5) L7(-5.5,1.5) L8(-4.5,1.5) L9(-3.5,1.5) L10(-2.5,1.5) L11(-1.5,1.5) L12(-0.5,1.5) L13(0.5,1.5) L14(1.5,1.5) L15(2.5,1.5) L16(3.5,1.5) L17(4.5,1.5) L18(5.5,1.5) L19(6.5,1.5) L20(7.5,1.5) L21(8.5,1.5) L22(9.5,1.5) L23(10.5,1.5) L24(11.5,1.5) M1(-11.5,0.5) M2(-10.5,0.5) M3(-9.5,0.5) M4(-8.5,0.5) M5(-7.5,0.5) M6(-6.5,0.5) M7(-5.5,0.5) M8(-4.5,0.5) M9(-3.5,0.5) M10(-2.5,0.5) M11(-1.5,0.5) M12(-0.5,0.5) M13(0.5,0.5) M14(1.5,0.5) M15(2.5,0.5) M16(3.5,0.5) M17(4.5,0.5) M18(5.5,0.5) M19(6.5,0.5) M20(7.5,0.5) M21(8.5,0.5) M22(9.5,0.5) M23(10.5,0.5) M24(11.5,0.5) N1(-11.5,-0.5) N2(-10.5,-0.5) N3(-9.5,-0.5) N4(-8.5,-0.5) N5(-7.5,-0.5) N6(-6.5,-0.5) N7(-5.5,-0.5) N8(-4.5,-0.5) N9(-3.5,-0.5) N10(-2.5,-0.5) N11(-1.5,-0.5) N12(-0.5,-0.5) N13(0.5,-0.5) N14(1.5,-0.5) N15(2.5,-0.5) N16(3.5,-0.5) N17(4.5,-0.5) N18(5.5,-0.5) N19(6.5,-0.5) N20(7.5,-0.5) N21(8.5,-0.5) N22(9.5,-0.5) N23(10.5,-0.5) N24(11.5,-0.5) P1(-11.5,-1.5) P2(-10.5,-1.5) P3(-9.5,-1.5) P4(-8.5,-1.5) P5(-7.5,-1.5) P6(-6.5,-1.5) P7(-5.5,-1.5) P8(-4.5,-1.5) P9(-3.5,-1.5) P10(-2.5,-1.5) P11(-1.5,-1.5) P12(-0.5,-1.5) P13(0.5,-1.5) P14(1.5,-1.5) P15(2.5,-1.5) P16(3.5,-1.5) P17(4.5,-1.5) P18(5.5,-1.5) P19(6.5,-1.5) P20(7.5,-1.5) P21(8.5,-1.5) P22(9.5,-1.5) P23(10.5,-1.5) P24(11.5,-1.5) R1(-11.5,-2.5) R2(-10.5,-2.5) R3(-9.5,-2.5) R4(-8.5,-2.5) R5(-7.5,-2.5) R6(-6.5,-2.5) R7(-5.5,-2.5) R8(-4.5,-2.5) R9(-3.5,-2.5) R10(-2.5,-2.5) R11(-1.5,-2.5) R12(-0.5,-2.5) R13(0.5,-2.5) R14(1.5,-2.5) R15(2.5,-2.5) R16(3.5,-2.5) R17(4.5,-2.5) R18(5.5,-2.5) R19(6.5,-2.5) R20(7.5,-2.5) R21(8.5,-2.5) R22(9.5,-2.5) R23(10.5,-2.5) R24(11.5,-2.5) T1(-11.5,-3.5) T2(-10.5,-3.5) T3(-9.5,-3.5) T4(-8.5,-3.5) T5(-7.5,-3.5) T6(-6.5,-3.5) T7(-5.5,-3.5) T8(-4.5,-3.5) T9(-3.5,-3.5) T10(-2.5,-3.5) T11(-1.5,-3.5) T12(-0.5,-3.5) T13(0.5,-3.5) T14(1.5,-3.5) T15(2.5,-3.5) T16(3.5,-3.5) T17(4.5,-3.5) T18(5.5,-3.5) T19(6.5,-3.5) T20(7.5,-3.5) T21(8.5,-3.5) T22(9.5,-3.5) T23(10.5,-3.5) T24(11.5,-3.5) U1(-11.5,-4.5) U2(-10.5,-4.5) U3(-9.5,-4.5) U4(-8.5,-4.5) U5(-7.5,-4.5) U6(-6.5,-4.5) U7(-5.5,-4.5) U8(-4.5,-4.5) U9(-3.5,-4.5) U10(-2.5,-4.5) U11(-1.5,-4.5) U12(-0.5,-4.5) U13(0.5,-4.5) U14(1.5,-4.5) U15(2.5,-4.5) U16(3.5,-4.5) U17(4.5,-4.5) U18(5.5,-4.5) U19(6.5,-4.5) U20(7.5,-4.5) U21(8.5,-4.5) U22(9.5,-4.5) U23(10.5,-4.5) U24(11.5,-4.5) V1(-11.5,-5.5) V2(-10.5,-5.5) V3(-9.5,-5.5) V4(-8.5,-5.5) V5(-7.5,-5.5) V6(-6.5,-5.5) V7(-5.5,-5.5) V8(-4.5,-5.5) V9(-3.5,-5.5) V10(-2.5,-5.5) V11(-1.5,-5.5) V12(-0.5,-5.5) V13(0.5,-5.5) V14(1.5,-5.5) V15(2.5,-5.5) V16(3.5,-5.5) V17(4.5,-5.5) V18(5.5,-5.5) V19(6.5,-5.5) V20(7.5,-5.5) V21(8.5,-5.5) V22(9.5,-5.5) V23(10.5,-5.5) V24(11.5,-5.5) W1(-11.5,-6.5) W2(-10.5,-6.5) W3(-9.5,-6.5) W4(-8.5,-6.5) W5(-7.5,-6.5) W6(-6.5,-6.5) W7(-5.5,-6.5) W8(-4.5,-6.5) W9(-3.5,-6.5) W10(-2.5,-6.5) W11(-1.5,-6.5) W12(-0.5,-6.5) W13(0.5,-6.5) W14(1.5,-6.5) W15(2.5,-6.5) W16(3.5,-6.5) W17(4.5,-6.5) W18(5.5,-6.5) W19(6.5,-6.5) W20(7.5,-6.5) W21(8.5,-6.5) W22(9.5,-6.5) W23(10.5,-6.5) W24(11.5,-6.5) Y1(-11.5,-7.5) Y2(-10.5,-7.5) Y3(-9.5,-7.5) Y4(-8.5,-7.5) Y5(-7.5,-7.5) Y6(-6.5,-7.5) Y7(-5.5,-7.5) Y8(-4.5,-7.5) Y9(-3.5,-7.5) Y10(-2.5,-7.5) Y11(-1.5,-7.5) Y12(-0.5,-7.5) Y13(0.5,-7.5) Y14(1.5,-7.5) Y15(2.5,-7.5) Y16(3.5,-7.5) Y17(4.5,-7.5) Y18(5.5,-7.5) Y19(6.5,-7.5) Y20(7.5,-7.5) Y21(8.5,-7.5) Y22(9.5,-7.5) Y23(10.5,-7.5) Y24(11.5,-7.5)
Top Overlay:
  circle w0.25: c-13.15,11.5 r0.125
  region: -11.525,12.5 -12.5,11.525 -12.5,12.5
  lines w0.2: -12.5,11.525 -11.525,12.5 ; -12.5,-12.5 -12.5,12.5 12.5,12.5 12.5,-12.5 -12.5,-12.5
Mechanical 13:
  lines w0.1: -12.5,-12.5 -12.5,12.5 12.5,12.5 12.5,-12.5 -12.5,-12.5
Mechanical 15:
  lines w0.1: -0.5,0 0.5,0 ; 0,-0.5 0,0.5 ; -13.5,-13.5 -13.5,13.5 13.5,13.5 13.5,-13.5 -13.5,-13.5
3D body: height 0, standoff 0, extent -12.5,-12.5 12.5,12.5

## BGA100P25X25-625 [mm] "BGA, 625-Leads, Body 27x27mm, Pitch 1mm"
height 3.5
pads (625):
  round 0.5 smd: A1(-12,12) A2(-11,12) A3(-10,12) A4(-9,12) A5(-8,12) A6(-7,12) A7(-6,12) A8(-5,12) A9(-4,12) A10(-3,12) A11(-2,12) A12(-1,12) A13(0,12) A14(1,12) A15(2,12) A16(3,12) A17(4,12) A18(5,12) A19(6,12) A20(7,12) A21(8,12) A22(9,12) A23(10,12) A24(11,12) A25(12,12) AA1(-12,-8) AA2(-11,-8) AA3(-10,-8) AA4(-9,-8) AA5(-8,-8) AA6(-7,-8) AA7(-6,-8) AA8(-5,-8) AA9(-4,-8) AA10(-3,-8) AA11(-2,-8) AA12(-1,-8) AA13(0,-8) AA14(1,-8) AA15(2,-8) AA16(3,-8) AA17(4,-8) AA18(5,-8) AA19(6,-8) AA20(7,-8) AA21(8,-8) AA22(9,-8) AA23(10,-8) AA24(11,-8) AA25(12,-8) AB1(-12,-9) AB2(-11,-9) AB3(-10,-9) AB4(-9,-9) AB5(-8,-9) AB6(-7,-9) AB7(-6,-9) AB8(-5,-9) AB9(-4,-9) AB10(-3,-9) AB11(-2,-9) AB12(-1,-9) AB13(0,-9) AB14(1,-9) AB15(2,-9) AB16(3,-9) AB17(4,-9) AB18(5,-9) AB19(6,-9) AB20(7,-9) AB21(8,-9) AB22(9,-9) AB23(10,-9) AB24(11,-9) AB25(12,-9) AC1(-12,-10) AC2(-11,-10) AC3(-10,-10) AC4(-9,-10) AC5(-8,-10) AC6(-7,-10) AC7(-6,-10) AC8(-5,-10) AC9(-4,-10) AC10(-3,-10) AC11(-2,-10) AC12(-1,-10) AC13(0,-10) AC14(1,-10) AC15(2,-10) AC16(3,-10) AC17(4,-10) AC18(5,-10) AC19(6,-10) AC20(7,-10) AC21(8,-10) AC22(9,-10) AC23(10,-10) AC24(11,-10) AC25(12,-10) AD1(-12,-11) AD2(-11,-11) AD3(-10,-11) AD4(-9,-11) AD5(-8,-11) AD6(-7,-11) AD7(-6,-11) AD8(-5,-11) AD9(-4,-11) AD10(-3,-11) AD11(-2,-11) AD12(-1,-11) AD13(0,-11) AD14(1,-11) AD15(2,-11) AD16(3,-11) AD17(4,-11) AD18(5,-11) AD19(6,-11) AD20(7,-11) AD21(8,-11) AD22(9,-11) AD23(10,-11) AD24(11,-11) AD25(12,-11) AE1(-12,-12) AE2(-11,-12) AE3(-10,-12) AE4(-9,-12) AE5(-8,-12) AE6(-7,-12) AE7(-6,-12) AE8(-5,-12) AE9(-4,-12) AE10(-3,-12) AE11(-2,-12) AE12(-1,-12) AE13(0,-12) AE14(1,-12) AE15(2,-12) AE16(3,-12) AE17(4,-12) AE18(5,-12) AE19(6,-12) AE20(7,-12) AE21(8,-12) AE22(9,-12) AE23(10,-12) AE24(11,-12) AE25(12,-12) B1(-12,11) B2(-11,11) B3(-10,11) B4(-9,11) B5(-8,11) B6(-7,11) B7(-6,11) B8(-5,11) B9(-4,11) B10(-3,11) B11(-2,11) B12(-1,11) B13(0,11) B14(1,11) B15(2,11) B16(3,11) B17(4,11) B18(5,11) B19(6,11) B20(7,11) B21(8,11) B22(9,11) B23(10,11) B24(11,11) B25(12,11) C1(-12,10) C2(-11,10) C3(-10,10) C4(-9,10) C5(-8,10) C6(-7,10) C7(-6,10) C8(-5,10) C9(-4,10) C10(-3,10) C11(-2,10) C12(-1,10) C13(0,10) C14(1,10) C15(2,10) C16(3,10) C17(4,10) C18(5,10) C19(6,10) C20(7,10) C21(8,10) C22(9,10) C23(10,10) C24(11,10) C25(12,10) D1(-12,9) D2(-11,9) D3(-10,9) D4(-9,9) D5(-8,9) D6(-7,9) D7(-6,9) D8(-5,9) D9(-4,9) D10(-3,9) D11(-2,9) D12(-1,9) D13(0,9) D14(1,9) D15(2,9) D16(3,9) D17(4,9) D18(5,9) D19(6,9) D20(7,9) D21(8,9) D22(9,9) D23(10,9) D24(11,9) D25(12,9) E1(-12,8) E2(-11,8) E3(-10,8) E4(-9,8) E5(-8,8) E6(-7,8) E7(-6,8) E8(-5,8) E9(-4,8) E10(-3,8) E11(-2,8) E12(-1,8) E13(0,8) E14(1,8) E15(2,8) E16(3,8) E17(4,8) E18(5,8) E19(6,8) E20(7,8) E21(8,8) E22(9,8) E23(10,8) E24(11,8) E25(12,8) F1(-12,7) F2(-11,7) F3(-10,7) F4(-9,7) F5(-8,7) F6(-7,7) F7(-6,7) F8(-5,7) F9(-4,7) F10(-3,7) F11(-2,7) F12(-1,7) F13(0,7) F14(1,7) F15(2,7) F16(3,7) F17(4,7) F18(5,7) F19(6,7) F20(7,7) F21(8,7) F22(9,7) F23(10,7) F24(11,7) F25(12,7) G1(-12,6) G2(-11,6) G3(-10,6) G4(-9,6) G5(-8,6) G6(-7,6) G7(-6,6) G8(-5,6) G9(-4,6) G10(-3,6) G11(-2,6) G12(-1,6) G13(0,6) G14(1,6) G15(2,6) G16(3,6) G17(4,6) G18(5,6) G19(6,6) G20(7,6) G21(8,6) G22(9,6) G23(10,6) G24(11,6) G25(12,6) H1(-12,5) H2(-11,5) H3(-10,5) H4(-9,5) H5(-8,5) H6(-7,5) H7(-6,5) H8(-5,5) H9(-4,5) H10(-3,5) H11(-2,5) H12(-1,5) H13(0,5) H14(1,5) H15(2,5) H16(3,5) H17(4,5) H18(5,5) H19(6,5) H20(7,5) H21(8,5) H22(9,5) H23(10,5) H24(11,5) H25(12,5) J1(-12,4) J2(-11,4) J3(-10,4) J4(-9,4) J5(-8,4) J6(-7,4) J7(-6,4) J8(-5,4) J9(-4,4) J10(-3,4) J11(-2,4) J12(-1,4) J13(0,4) J14(1,4) J15(2,4) J16(3,4) J17(4,4) J18(5,4) J19(6,4) J20(7,4) J21(8,4) J22(9,4) J23(10,4) J24(11,4) J25(12,4) K1(-12,3) K2(-11,3) K3(-10,3) K4(-9,3) K5(-8,3) K6(-7,3) K7(-6,3) K8(-5,3) K9(-4,3) K10(-3,3) K11(-2,3) K12(-1,3) K13(0,3) K14(1,3) K15(2,3) K16(3,3) K17(4,3) K18(5,3) K19(6,3) K20(7,3) K21(8,3) K22(9,3) K23(10,3) K24(11,3) K25(12,3) L1(-12,2) L2(-11,2) L3(-10,2) L4(-9,2) L5(-8,2) L6(-7,2) L7(-6,2) L8(-5,2) L9(-4,2) L10(-3,2) L11(-2,2) L12(-1,2) L13(0,2) L14(1,2) L15(2,2) L16(3,2) L17(4,2) L18(5,2) L19(6,2) L20(7,2) L21(8,2) L22(9,2) L23(10,2) L24(11,2) L25(12,2) M1(-12,1) M2(-11,1) M3(-10,1) M4(-9,1) M5(-8,1) M6(-7,1) M7(-6,1) M8(-5,1) M9(-4,1) M10(-3,1) M11(-2,1) M12(-1,1) M13(0,1) M14(1,1) M15(2,1) M16(3,1) M17(4,1) M18(5,1) M19(6,1) M20(7,1) M21(8,1) M22(9,1) M23(10,1) M24(11,1) M25(12,1) N1(-12,0) N2(-11,0) N3(-10,0) N4(-9,0) N5(-8,0) N6(-7,0) N7(-6,0) N8(-5,0) N9(-4,0) N10(-3,0) N11(-2,0) N12(-1,0) N13(0,0) N14(1,0) N15(2,0) N16(3,0) N17(4,0) N18(5,0) N19(6,0) N20(7,0) N21(8,0) N22(9,0) N23(10,0) N24(11,0) N25(12,0) P1(-12,-1) P2(-11,-1) P3(-10,-1) P4(-9,-1) P5(-8,-1) P6(-7,-1) P7(-6,-1) P8(-5,-1) P9(-4,-1) P10(-3,-1) P11(-2,-1) P12(-1,-1) P13(0,-1) P14(1,-1) P15(2,-1) P16(3,-1) P17(4,-1) P18(5,-1) P19(6,-1) P20(7,-1) P21(8,-1) P22(9,-1) P23(10,-1) P24(11,-1) P25(12,-1) R1(-12,-2) R2(-11,-2) R3(-10,-2) R4(-9,-2) R5(-8,-2) R6(-7,-2) R7(-6,-2) R8(-5,-2) R9(-4,-2) R10(-3,-2) R11(-2,-2) R12(-1,-2) R13(0,-2) R14(1,-2) R15(2,-2) R16(3,-2) R17(4,-2) R18(5,-2) R19(6,-2) R20(7,-2) R21(8,-2) R22(9,-2) R23(10,-2) R24(11,-2) R25(12,-2) T1(-12,-3) T2(-11,-3) T3(-10,-3) T4(-9,-3) T5(-8,-3) T6(-7,-3) T7(-6,-3) T8(-5,-3) T9(-4,-3) T10(-3,-3) T11(-2,-3) T12(-1,-3) T13(0,-3) T14(1,-3) T15(2,-3) T16(3,-3) T17(4,-3) T18(5,-3) T19(6,-3) T20(7,-3) T21(8,-3) T22(9,-3) T23(10,-3) T24(11,-3) T25(12,-3) U1(-12,-4) U2(-11,-4) U3(-10,-4) U4(-9,-4) U5(-8,-4) U6(-7,-4) U7(-6,-4) U8(-5,-4) U9(-4,-4) U10(-3,-4) U11(-2,-4) U12(-1,-4) U13(0,-4) U14(1,-4) U15(2,-4) U16(3,-4) U17(4,-4) U18(5,-4) U19(6,-4) U20(7,-4) U21(8,-4) U22(9,-4) U23(10,-4) U24(11,-4) U25(12,-4) V1(-12,-5) V2(-11,-5) V3(-10,-5) V4(-9,-5) V5(-8,-5) V6(-7,-5) V7(-6,-5) V8(-5,-5) V9(-4,-5) V10(-3,-5) V11(-2,-5) V12(-1,-5) V13(0,-5) V14(1,-5) V15(2,-5) V16(3,-5) V17(4,-5) V18(5,-5) V19(6,-5) V20(7,-5) V21(8,-5) V22(9,-5) V23(10,-5) V24(11,-5) V25(12,-5) W1(-12,-6) W2(-11,-6) W3(-10,-6) W4(-9,-6) W5(-8,-6) W6(-7,-6) W7(-6,-6) W8(-5,-6) W9(-4,-6) W10(-3,-6) W11(-2,-6) W12(-1,-6) W13(0,-6) W14(1,-6) W15(2,-6) W16(3,-6) W17(4,-6) W18(5,-6) W19(6,-6) W20(7,-6) W21(8,-6) W22(9,-6) W23(10,-6) W24(11,-6) W25(12,-6) Y1(-12,-7) Y2(-11,-7) Y3(-10,-7) Y4(-9,-7) Y5(-8,-7) Y6(-7,-7) Y7(-6,-7) Y8(-5,-7) Y9(-4,-7) Y10(-3,-7) Y11(-2,-7) Y12(-1,-7) Y13(0,-7) Y14(1,-7) Y15(2,-7) Y16(3,-7) Y17(4,-7) Y18(5,-7) Y19(6,-7) Y20(7,-7) Y21(8,-7) Y22(9,-7) Y23(10,-7) Y24(11,-7) Y25(12,-7)
Top Overlay:
  circle w0.25: c-14.15,12 r0.125
  region: -12.5,13.5 -13.5,12.5 -13.5,13.5
  lines w0.2: -13.5,12.5 -12.5,13.5 ; -13.5,-13.5 -13.5,13.5 13.5,13.5 13.5,-13.5 -13.5,-13.5
Mechanical 13:
  lines w0.1: -13.5,-13.5 -13.5,13.5 13.5,13.5 13.5,-13.5 -13.5,-13.5
Mechanical 15:
  lines w0.1: -0.5,0 0.5,0 ; 0,-0.5 0,0.5 ; -14.5,-14.5 -14.5,14.5 14.5,14.5 14.5,-14.5 -14.5,-14.5
3D body: height 0, standoff 0, extent -13.5,-13.5 13.5,13.5

## BGA100P26X26-352 [mm] "352-Ball Ball Grid Array 1 mm Pitch"
height 3.5
pads (352):
  round 0.5 smd: A1(-12.5,12.5) A2(-11.5,12.5) A3(-10.5,12.5) A4(-9.5,12.5) A5(-8.5,12.5) A6(-7.5,12.5) A7(-6.5,12.5) A8(-5.5,12.5) A9(-4.5,12.5) A10(-3.5,12.5) A11(-2.5,12.5) A12(-1.5,12.5) A13(-0.5,12.5) A14(0.5,12.5) A15(1.5,12.5) A16(2.5,12.5) A17(3.5,12.5) A18(4.5,12.5) A19(5.5,12.5) A20(6.5,12.5) A21(7.5,12.5) A22(8.5,12.5) A23(9.5,12.5) A24(10.5,12.5) A25(11.5,12.5) A26(12.5,12.5) AA1(-12.5,-7.5) AA2(-11.5,-7.5) AA3(-10.5,-7.5) AA4(-9.5,-7.5) AA23(9.5,-7.5) AA24(10.5,-7.5) AA25(11.5,-7.5) AA26(12.5,-7.5) AB1(-12.5,-8.5) AB2(-11.5,-8.5) AB3(-10.5,-8.5) AB4(-9.5,-8.5) AB23(9.5,-8.5) AB24(10.5,-8.5) AB25(11.5,-8.5) AB26(12.5,-8.5) AC1(-12.5,-9.5) AC2(-11.5,-9.5) AC3(-10.5,-9.5) AC4(-9.5,-9.5) AC5(-8.5,-9.5) AC6(-7.5,-9.5) AC7(-6.5,-9.5) AC8(-5.5,-9.5) AC9(-4.5,-9.5) AC10(-3.5,-9.5) AC11(-2.5,-9.5) AC12(-1.5,-9.5) AC13(-0.5,-9.5) AC14(0.5,-9.5) AC15(1.5,-9.5) AC16(2.5,-9.5) AC17(3.5,-9.5) AC18(4.5,-9.5) AC19(5.5,-9.5) AC20(6.5,-9.5) AC21(7.5,-9.5) AC22(8.5,-9.5) AC23(9.5,-9.5) AC24(10.5,-9.5) AC25(11.5,-9.5) AC26(12.5,-9.5) AD1(-12.5,-10.5) AD2(-11.5,-10.5) AD3(-10.5,-10.5) AD4(-9.5,-10.5) AD5(-8.5,-10.5) AD6(-7.5,-10.5) AD7(-6.5,-10.5) AD8(-5.5,-10.5) AD9(-4.5,-10.5) AD10(-3.5,-10.5) AD11(-2.5,-10.5) AD12(-1.5,-10.5) AD13(-0.5,-10.5) AD14(0.5,-10.5) AD15(1.5,-10.5) AD16(2.5,-10.5) AD17(3.5,-10.5) AD18(4.5,-10.5) AD19(5.5,-10.5) AD20(6.5,-10.5) AD21(7.5,-10.5) AD22(8.5,-10.5) AD23(9.5,-10.5) AD24(10.5,-10.5) AD25(11.5,-10.5) AD26(12.5,-10.5) AE1(-12.5,-11.5) AE2(-11.5,-11.5) AE3(-10.5,-11.5) AE4(-9.5,-11.5) AE5(-8.5,-11.5) AE6(-7.5,-11.5) AE7(-6.5,-11.5) AE8(-5.5,-11.5) AE9(-4.5,-11.5) AE10(-3.5,-11.5) AE11(-2.5,-11.5) AE12(-1.5,-11.5) AE13(-0.5,-11.5) AE14(0.5,-11.5) AE15(1.5,-11.5) AE16(2.5,-11.5) AE17(3.5,-11.5) AE18(4.5,-11.5) AE19(5.5,-11.5) AE20(6.5,-11.5) AE21(7.5,-11.5) AE22(8.5,-11.5) AE23(9.5,-11.5) AE24(10.5,-11.5) AE25(11.5,-11.5) AE26(12.5,-11.5) AF1(-12.5,-12.5) AF2(-11.5,-12.5) AF3(-10.5,-12.5) AF4(-9.5,-12.5) AF5(-8.5,-12.5) AF6(-7.5,-12.5) AF7(-6.5,-12.5) AF8(-5.5,-12.5) AF9(-4.5,-12.5) AF10(-3.5,-12.5) AF11(-2.5,-12.5) AF12(-1.5,-12.5) AF13(-0.5,-12.5) AF14(0.5,-12.5) AF15(1.5,-12.5) AF16(2.5,-12.5) AF17(3.5,-12.5) AF18(4.5,-12.5) AF19(5.5,-12.5) AF20(6.5,-12.5) AF21(7.5,-12.5) AF22(8.5,-12.5) AF23(9.5,-12.5) AF24(10.5,-12.5) AF25(11.5,-12.5) AF26(12.5,-12.5) B1(-12.5,11.5) B2(-11.5,11.5) B3(-10.5,11.5) B4(-9.5,11.5) B5(-8.5,11.5) B6(-7.5,11.5) B7(-6.5,11.5) B8(-5.5,11.5) B9(-4.5,11.5) B10(-3.5,11.5) B11(-2.5,11.5) B12(-1.5,11.5) B13(-0.5,11.5) B14(0.5,11.5) B15(1.5,11.5) B16(2.5,11.5) B17(3.5,11.5) B18(4.5,11.5) B19(5.5,11.5) B20(6.5,11.5) B21(7.5,11.5) B22(8.5,11.5) B23(9.5,11.5) B24(10.5,11.5) B25(11.5,11.5) B26(12.5,11.5) C1(-12.5,10.5) C2(-11.5,10.5) C3(-10.5,10.5) C4(-9.5,10.5) C5(-8.5,10.5) C6(-7.5,10.5) C7(-6.5,10.5) C8(-5.5,10.5) C9(-4.5,10.5) C10(-3.5,10.5) C11(-2.5,10.5) C12(-1.5,10.5) C13(-0.5,10.5) C14(0.5,10.5) C15(1.5,10.5) C16(2.5,10.5) C17(3.5,10.5) C18(4.5,10.5) C19(5.5,10.5) C20(6.5,10.5) C21(7.5,10.5) C22(8.5,10.5) C23(9.5,10.5) C24(10.5,10.5) C25(11.5,10.5) C26(12.5,10.5) D1(-12.5,9.5) D2(-11.5,9.5) D3(-10.5,9.5) D4(-9.5,9.5) D5(-8.5,9.5) D6(-7.5,9.5) D7(-6.5,9.5) D8(-5.5,9.5) D9(-4.5,9.5) D10(-3.5,9.5) D11(-2.5,9.5) D12(-1.5,9.5) D13(-0.5,9.5) D14(0.5,9.5) D15(1.5,9.5) D16(2.5,9.5) D17(3.5,9.5) D18(4.5,9.5) D19(5.5,9.5) D20(6.5,9.5) D21(7.5,9.5) D22(8.5,9.5) D23(9.5,9.5) D24(10.5,9.5) D25(11.5,9.5) D26(12.5,9.5) E1(-12.5,8.5) E2(-11.5,8.5) E3(-10.5,8.5) E4(-9.5,8.5) E23(9.5,8.5) E24(10.5,8.5) E25(11.5,8.5) E26(12.5,8.5) F1(-12.5,7.5) F2(-11.5,7.5) F3(-10.5,7.5) F4(-9.5,7.5) F23(9.5,7.5) F24(10.5,7.5) F25(11.5,7.5) F26(12.5,7.5) G1(-12.5,6.5) G2(-11.5,6.5) G3(-10.5,6.5) G4(-9.5,6.5) G23(9.5,6.5) G24(10.5,6.5) G25(11.5,6.5) G26(12.5,6.5) H1(-12.5,5.5) H2(-11.5,5.5) H3(-10.5,5.5) H4(-9.5,5.5) H23(9.5,5.5) H24(10.5,5.5) H25(11.5,5.5) H26(12.5,5.5) J1(-12.5,4.5) J2(-11.5,4.5) J3(-10.5,4.5) J4(-9.5,4.5) J23(9.5,4.5) J24(10.5,4.5) J25(11.5,4.5) J26(12.5,4.5) K1(-12.5,3.5) K2(-11.5,3.5) K3(-10.5,3.5) K4(-9.5,3.5) K23(9.5,3.5) K24(10.5,3.5) K25(11.5,3.5) K26(12.5,3.5) L1(-12.5,2.5) L2(-11.5,2.5) L3(-10.5,2.5) L4(-9.5,2.5) L23(9.5,2.5) L24(10.5,2.5) L25(11.5,2.5) L26(12.5,2.5) M1(-12.5,1.5) M2(-11.5,1.5) M3(-10.5,1.5) M4(-9.5,1.5) M23(9.5,1.5) M24(10.5,1.5) M25(11.5,1.5) M26(12.5,1.5) N1(-12.5,0.5) N2(-11.5,0.5) N3(-10.5,0.5) N4(-9.5,0.5) N23(9.5,0.5) N24(10.5,0.5) N25(11.5,0.5) N26(12.5,0.5) P1(-12.5,-0.5) P2(-11.5,-0.5) P3(-10.5,-0.5) P4(-9.5,-0.5) P23(9.5,-0.5) P24(10.5,-0.5) P25(11.5,-0.5) P26(12.5,-0.5) R1(-12.5,-1.5) R2(-11.5,-1.5) R3(-10.5,-1.5) R4(-9.5,-1.5) R23(9.5,-1.5) R24(10.5,-1.5) R25(11.5,-1.5) R26(12.5,-1.5) T1(-12.5,-2.5) T2(-11.5,-2.5) T3(-10.5,-2.5) T4(-9.5,-2.5) T23(9.5,-2.5) T24(10.5,-2.5) T25(11.5,-2.5) T26(12.5,-2.5) U1(-12.5,-3.5) U2(-11.5,-3.5) U3(-10.5,-3.5) U4(-9.5,-3.5) U23(9.5,-3.5) U24(10.5,-3.5) U25(11.5,-3.5) U26(12.5,-3.5) V1(-12.5,-4.5) V2(-11.5,-4.5) V3(-10.5,-4.5) V4(-9.5,-4.5) V23(9.5,-4.5) V24(10.5,-4.5) V25(11.5,-4.5) V26(12.5,-4.5) W1(-12.5,-5.5) W2(-11.5,-5.5) W3(-10.5,-5.5) W4(-9.5,-5.5) W23(9.5,-5.5) W24(10.5,-5.5) W25(11.5,-5.5) W26(12.5,-5.5) Y1(-12.5,-6.5) Y2(-11.5,-6.5) Y3(-10.5,-6.5) Y4(-9.5,-6.5) Y23(9.5,-6.5) Y24(10.5,-6.5) Y25(11.5,-6.5) Y26(12.5,-6.5)
Top Overlay:
  circle w0.25: c-14.15,12.5 r0.125
  region: -12.5,13.5 -13.5,12.5 -13.5,13.5
  lines w0.2: -13.5,12.5 -12.5,13.5 ; -13.5,-13.5 -13.5,13.5 13.5,13.5 13.5,-13.5 -13.5,-13.5
Mechanical 13:
  lines w0.1: -13.5,-13.5 -13.5,13.5 13.5,13.5 13.5,-13.5 -13.5,-13.5
Mechanical 15:
  lines w0.1: -0.5,0 0.5,0 ; 0,-0.5 0,0.5 ; -14.5,-14.5 -14.5,14.5 14.5,14.5 14.5,-14.5 -14.5,-14.5
3D body: height 0, standoff 0, extent -13.5,-13.5 13.5,13.5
